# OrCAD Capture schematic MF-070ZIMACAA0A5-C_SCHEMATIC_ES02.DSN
size Custom; title: MF-070ZIMACAA0A5-C POWER BOARD; rev: ES02; note: 311-0701000005
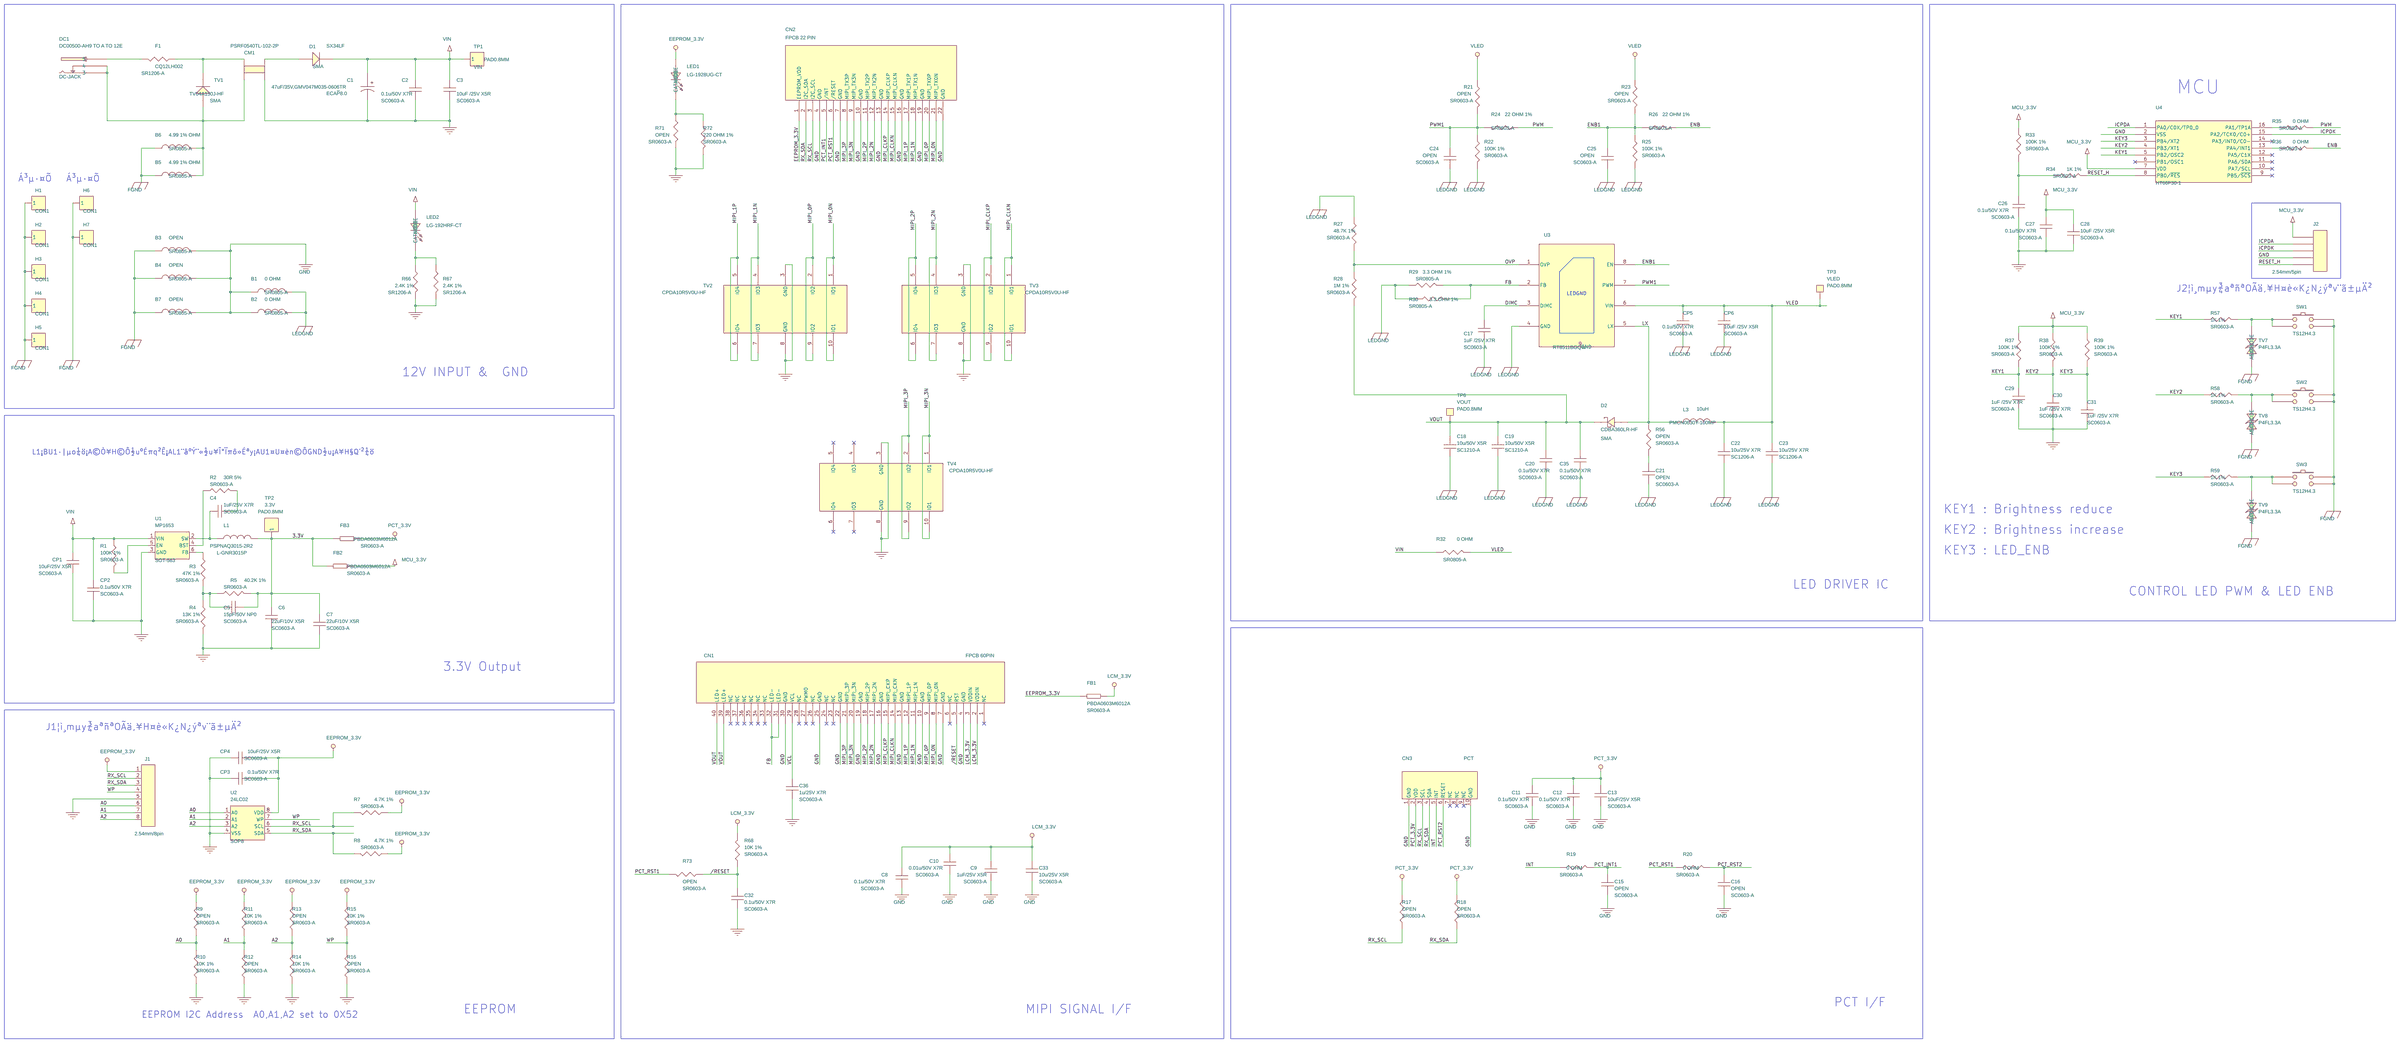
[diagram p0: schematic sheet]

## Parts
B1  0 OHM  [SR0805-A]
B2  0 OHM  [SR0805-A]
B3  OPEN  [SR0805-A]
B4  OPEN  [SR0805-A]
B5  4.99 1% OHM  [SR0805-A]
B6  4.99 1% OHM  [SR0805-A]
B7  OPEN  [SR0805-A]
C1  47uF/35V,GMV047M035-0606TR  [ECAP\8.0]
C2  0.1u/50V X7R  [SC0603-A]
C3  10uF /25V X5R  [SC0603-A]
C4  1uF/25V X7R  [SC0603-A]
C5  15pF/50V NP0  [SC0603-A]
C6  22uF/10V X5R  [SC0603-A]
C7  22uF/10V X5R  [SC0603-A]
C8  0.1u/50V X7R  [SC0603-A]
C9  1uF/25V X5R  [SC0603-A]
C10  0.01u/50V X7R  [SC0603-A]
C11  0.1u/50V X7R  [SC0603-A]
C12  0.1u/50V X7R  [SC0603-A]
C13  10uF/25V X5R  [SC0603-A]
C15  OPEN  [SC0603-A]
C16  OPEN  [SC0603-A]
C17  1uF /25V X7R  [SC0603-A]
C18  10u/50V X5R  [SC1210-A]
C19  10u/50V X5R  [SC1210-A]
C20  0.1u/50V X7R  [SC0603-A]
C21  OPEN  [SC0603-A]
C22  10u/25V X7R  [SC1206-A]
C23  10u/25V X7R  [SC1206-A]
C24  OPEN  [SC0603-A]
C25  OPEN  [SC0603-A]
C26  0.1u/50V X7R  [SC0603-A]
C27  0.1u/50V X7R  [SC0603-A]
C28  10uF /25V X5R  [SC0603-A]
C29  1uF /25V X7R  [SC0603-A]
C30  1uF /25V X7R  [SC0603-A]
C31  1uF /25V X7R  [SC0603-A]
C32  0.1u/50V X7R  [SC0603-A]
C33  10u/25V X5R  [SC0603-A]
C35  0.1u/50V X7R  [SC0603-A]
C36  1u/25V X7R  [SC0603-A]
CM1  PSRF0540TL-102-2P  [GDLW0504P]
CN1  FPCB 60PIN  [IC-HSD035E8N1]
CN2  FPCB 22 PIN  [IC-HSD035E8N1]
CN3  PCT  [FPCB 10 PIN]
CP1  10uF/25V X5R  [SC0603-A]
CP2  0.1u/50V X7R  [SC0603-A]
CP3  0.1u/50V X7R  [SC0603-A]
CP4  10uF/25V X5R  [SC0603-A]
CP5  0.1u/50V X7R  [SC0603-A]
CP6  10uF /25V X5R  [SC0603-A]
D1  SX34LF  [SMA]
D2  CDBA360LR-HF  [SMA]
DC1  DC00500-AH9 TO A TO 12E  [DC-JACK]
F1  CQ12LH002  [SR1206-A]
FB1  PBDA0603M6012A  [SR0603-A]
FB2  PBDA0603M6012A  [SR0603-A]
FB3  PBDA0603M6012A  [SR0603-A]
H1  CON1  [HOLE]
H2  CON1  [HOLE]
H3  CON1  [HOLE]
H4  CON1  [HOLE]
H5  CON1  [HOLE]
H6  CON1  [HOLE]
H7  CON1  [HOLE]
J1  2.54mm/8pin  [SIP\8P]
J2  2.54mm/5pin  [SIP\5P]
L1  PSPNAQ3015-2R2  [L-GNR3015P]
L3  10uH  [PMCN0630Y-100MP]
LED1  LG-1928UG-CT
LED2  LG-192HRF-CT
R1  100K 1%  [SR0603-A]
R2  30R 5%  [SR0603-A]
R3  47K 1%  [SR0603-A]
R4  13K 1%  [SR0603-A]
R5  40.2K 1%  [SR0603-A]
R7  4.7K 1%  [SR0603-A]
R8  4.7K 1%  [SR0603-A]
R9  OPEN  [SR0603-A]
R10  10K 1%  [SR0603-A]
R11  10K 1%  [SR0603-A]
R12  OPEN  [SR0603-A]
R13  OPEN  [SR0603-A]
R14  10K 1%  [SR0603-A]
R15  10K 1%  [SR0603-A]
R16  OPEN  [SR0603-A]
R17  OPEN  [SR0603-A]
R18  OPEN  [SR0603-A]
R19  0 OHM  [SR0603-A]
R20  0 OHM  [SR0603-A]
R21  OPEN  [SR0603-A]
R22  100K 1%  [SR0603-A]
R23  OPEN  [SR0603-A]
R24  22 OHM 1%  [SR0603-A]
R25  100K 1%  [SR0603-A]
R26  22 OHM 1%  [SR0603-A]
R27  48.7K 1%  [SR0603-A]
R28  1M 1%  [SR0603-A]
R29  3.3 OHM 1%  [SR0805-A]
R30  3.3 OHM 1%  [SR0805-A]
R32  0 OHM  [SR0805-A]
R33  100K 1%  [SR0603-A]
R34  1K 1%  [SR0603-A]
R35  0 OHM  [SR0603-A]
R36  0 OHM  [SR0603-A]
R37  100K 1%  [SR0603-A]
R38  100K 1%  [SR0603-A]
R39  100K 1%  [SR0603-A]
R56  OPEN  [SR0603-A]
R57  1K 1%  [SR0603-A]
R58  1K 1%  [SR0603-A]
R59  1K 1%  [SR0603-A]
R66  2.4K 1%  [SR1206-A]
R67  2.4K 1%  [SR1206-A]
R68  10K 1%  [SR0603-A]
R71  OPEN  [SR0603-A]
R72  220 OHM 1%  [SR0603-A]
R73  OPEN  [SR0603-A]
SW1  TS12H4.3
SW2  TS12H4.3
SW3  TS12H4.3
TP1  VIN  [PAD0.8MM]
TP2  3.3V  [PAD0.8MM]
TP3  VLED  [PAD0.8MM]
TP6  VOUT  [PAD0.8MM]
TV1  TV04A150J-HF  [SMA]
TV2  CPDA10R5V0U-HF  [SGP2510P8]
TV3  CPDA10R5V0U-HF  [SGP2510P8]
TV4  CPDA10R5V0U-HF  [SGP2510P8]
TV7  P4FL3.3A  [DIO_DFN0201_0-4]
TV8  P4FL3.3A  [DIO_DFN0201_0-4]
TV9  P4FL3.3A  [DIO_DFN0201_0-4]
U1  MP1653  [SOT-563]
U2  24LC02  [SOP8]
U3  RT8511BGQW  [DFN3_8_0-65_2]
U4  HT66F30-1  [NSOP-16P]

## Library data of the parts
B1-B7 L3 = INDUCTOR
C1 = ECAP_POL: Part Number: 117-00-3057
C2 C3 CP3 CP4 = CAP_NP0603: Part Number: 117-00-3036
C4 C5 = CAP_NP0603: Part Number: 117-00-3003
C6 C7 CP1 CP2 = CAP_NP0603: Part Number: 117-00-3043
C8-C13 C15-C28 C32 C33 C35 C36 CP5 CP6 = CAP_NP
C29-C31 = CAP_NP0603: Part Number: 117-00-3040
CM1 = INDUCTOR_2
CN1 = HANNSTAR_HSD035E8N1_6
CN2 = HANNSTAR_HSD035E8N1_7
CN3 = CON1_3
D1 = DIODE_1
D2 = DIODE_SCHOTTKY
DC1 = DC005_0: Part Description: DC JACK,DC005; Part Number: 226-00-3088
F1 R21-R30 R32 R33 R37-R39 R56-R59 = R
FB1-FB3 = BEAD0805: Part Number: 647-00-3000
H1-H7 TP1 TP2 = CON1
J1 = CON5_0
J2 = CON4_0
L1 = INDUCTOR0805: Part Number: 647-01-3059
LED1 LED2 = LED
R1 R3 R4 R66 R67 R71 R72 = RES0603: Part Number: 737-00-3068
R2 R5 = RES0603: Part Number: 737-00-3070
R7-R20 R68 R73 = RES0603: Part Number: 737-00-3060
R34-R36 = RES0603: Part Number: 737-00-3008
SW1-SW3 = SW_PUSHBUTTON_0
TP3 TP6 = TP_0
TV1 = DIODE_2
TV2-TV4 = RClamp3324P
TV7-TV9 = DIODE_TVS_DUAL: DIODE 1CH ESD PROTECTION FOR USB TYPE-C AND THUNDERBOLT3 X2SON2; Chkd/date: MANIRAJA/230920; Crtd /date: ALVY/230920; Custom_Duty: 15%; Customs_HS_Code: 85412900; Footprint Ref: SOD-123; Library Path: Y:\MIS_DATABASE\Library\ALTIUM_TOOL\SCHEMATICS_PARTS\MS_DISCRETE_Library.schlib; Mfr_name: TEXAS INSTRUMENTS; Mfr_part_number: TPD1E01B04DPLT; Mistral Part No: 130020090037-R; Package: X2SON2; Part_type: DIODE\TVS; Project: AM64X_SKEVM; RoHS: RoHS; Temperature: -40°C+125°C; Tolerance: NA; Voltage: NA; Wattage: NA; Weight: 0.2mg; Datasheet: Y:\MIS_DATABASE\DATASHEETS\DISCRETES\DIODES\TPD1E01B04.PDF
U1 = TD6810_0: Part Description: TD6810; Part Number: 427-00-3007
U2 = AT24C08: Part Number: 427-00-3002
U3 = RT8511_0
U4 = PIC16F873_SO_2

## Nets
3.3V: C5.2 C6.1 C7.1 FB2.1 FB3.1 L1.2 R5.2 TP2.1
GND: B1.1 B2.1 B3.2 B4.2 B7.2 C1.2 C2.2 C3.2 C6.2 C7.2 C8.2 C9.2 C10.2 C11.2 C12.2 C13.2 C15.2 C16.2 C26.2 C27.2 C28.2 C29.2 C30.2 C31.2 C32.2 C33.2 C36.2 CM1.3 CN1.4(GND) CN1.7(GND) CN1.10(GND) CN1.13(GND) CN1.16(GND) CN1.19(GND) CN1.22(GND) CN1.25(GND) CN1.30(GND) CN2.4(GND) CN2.7(GND) CN2.10(GND) CN2.13(GND) CN2.16(GND) CN2.19(GND) CN2.22(GND) CN3.1(GND) CN3.10(GND) CP1.2 CP2.2 CP3.1 CP4.1 J1.5 J2.4 R4.2 R10.1 R12.1 R14.1 R16.1 R66.2 R67.2 R71.2 R72.2 TV2.3(GND) TV2.8(GND) TV3.3(GND) TV3.8(GND) TV4.3(GND) TV4.8(GND) U1.3(GND) U2.4(VSS) U3.9(GND) U4.2(VSS)
VIN: C1.1 C2.1 C3.1 CP1.1 CP2.1 D1.2 LED2.1(ANODE) R1.1 R32.1 TP1.1 U1.1(VIN)
/RESET: C32.1 CN1.5(RST) R68.1 R73.1
A0: J1.6 R9.1 R10.2 U2.1(A0)
A1: J1.7 R11.1 R12.2 U2.2(A1)
A2: J1.8 R13.1 R14.2 U2.3(A2)
DIMC: C17.2 U3.3(DIMC)
EEPROM_3.3V: CN2.1(EEPROM_VDD) CP3.2 CP4.2 FB1.1 J1.1 LED1.1(ANODE) R7.1 R8.1 R9.2 R11.2 R13.2 R15.2 U2.8(VDD)
ENB: R26.1 R36.1
ENB1: C25.1 R23.2 R25.1 R26.2 U3.8(EN)
FB: CN1.31(LED-) CN1.32(LED-) R29.2 R30.2 U3.2(FB)
FGND: B3.1 B4.1 B5.1 B6.1 B7.1 H1.1 H2.1 H3.1 H4.1 H5.1 H6.1 H7.1 SW1.C SW1.D SW2.C SW2.D SW3.C SW3.D TV7.2(ANODE) TV8.2(ANODE) TV9.2(ANODE)
ICPDA: J2.2 U4.1(PA0/C0X/TP0_0)
ICPDK: J2.3 U4.15(PA2/TCK0/C0+)
INT: CN3.5(INT) R19.1
KEY1: C29.1 R37.2 R57.1 U4.5(PB2/OSC2)
KEY2: C30.1 R38.2 R58.1 U4.4(PB3/XT1)
KEY3: C31.1 R39.2 R59.1 U4.3(PB4/XT2)
LCM_3.3V: C8.1 C9.1 C10.1 C33.1 CN1.2(VDDIN) CN1.3(VDDIN) FB1.2 R68.2
LEDGND: B1.2 B2.2 C17.1 C18.1 C19.1 C20.1 C21.2 C22.1 C23.1 C24.2 C25.2 C35.1 CP5.2 CP6.2 R22.2 R25.2 R27.1 R29.1 R30.1 U3.4(GND)
LX: D2.1(ANODE) L3.1 R56.1 U3.5(LX)
MCU_3.3V: C27.1 C28.1 FB2.2 J2.1 R33.1 R37.1 R38.1 R39.1 U4.7(VDD)
MIPI_0N: CN1.8(MIPI_0N) CN2.21(MIPI_TX0N) TV2.1(IO1) TV2.10(IO1)
MIPI_0P: CN1.9(MIPI_0P) CN2.20(MIPI_TX0P) TV2.2(IO2) TV2.9(IO2)
MIPI_1N: CN1.11(MIPI_1N) CN2.18(MIPI_TX1N) TV2.4(IO3) TV2.7(IO3)
MIPI_1P: CN1.12(MIPI_1P) CN2.17(MIPI_TX1P) TV2.5(IO4) TV2.6(IO4)
MIPI_2N: CN1.17(MIPI_2N) CN2.12(MIPI_TX2N) TV3.4(IO3) TV3.7(IO3)
MIPI_2P: CN1.18(MIPI_2P) CN2.11(MIPI_TX2P) TV3.5(IO4) TV3.6(IO4)
MIPI_3N: CN1.20(MIPI_3N) CN2.9(MIPI_TX3N) TV4.1(IO1) TV4.10(IO1)
MIPI_3P: CN1.21(MIPI_3P) CN2.8(MIPI_TX3P) TV4.2(IO2) TV4.9(IO2)
MIPI_CLKN: CN1.14(MIPI_CKN) CN2.15(MIPI_CLKN) TV3.1(IO1) TV3.10(IO1)
MIPI_CLKP: CN1.15(MIPI_CKP) CN2.14(MIPI_CLKP) TV3.2(IO2) TV3.9(IO2)
OVP: R27.2 R28.1 U3.1(OVP)
PCT_3.3V: C11.1 C12.1 C13.1 CN3.2(VDD) FB3.2 R17.2 R18.2
PCT_INT1: C15.1 CN2.5(/INT) R19.2
PCT_RST1: CN2.6(/RESET) R20.1 R73.2
PCT_RST2: C16.1 CN3.6(RESET) R20.2
PWM: R24.1 R35.1
PWM1: C24.1 R21.2 R22.1 R24.2 U3.7(PWM)
RESET_H: J2.5 R34.1 U4.8(PB0/~{RES})
RX_SCL: CN2.3(I2C_SCL) CN3.3(SCL) J1.2 R7.2 R17.1 U2.6(SCL)
RX_SDA: CN2.2(I2C_SDA) CN3.4(SDA) J1.3 R8.2 R18.1 U2.5(SDA)
VCL: C36.1 CN1.29(VCL)
VLED: C22.2 C23.2 CP5.1 CP6.1 L3.2 R21.1 R23.1 R32.2 TP3.1(TP) U3.6(VIN)
VOUT: C18.2 C19.2 C20.2 C35.2 CN1.39(LED+) CN1.40(LED+) D2.2(CATHODE) R28.2 TP6.1(TP)
WP: J1.4 R15.1 R16.2 U2.7(WP)
N14289089: DC1.5 F1.2
N14289101: CM1.1 F1.1 TV1.2
N14289105: CM1.2 D1.1
N14289125: B5.2 B6.2 CM1.4 DC1.3 DC1.4 TV1.1
N14506503: C21.1 R56.2
N14509647: R2.1 U1.4(BST)
N14509651: C4.2 R2.2
N14509727: C4.1 L1.1 U1.2(SW)
N14509879: R1.2 U1.5(EN)
N14509925: R3.1 U1.6(FB)
N14510061: C5.1 R3.2 R4.1 R5.1
N14543357: C26.1 R33.2 R34.2
N14572856: R36.2 U4.13(PA4/INT1)
N14573902: R57.2 SW1.A SW1.B TV7.1(CATHODE)
N14573940: R58.2 SW2.A SW2.B TV8.1(CATHODE)
N14573978: R59.2 SW3.A SW3.B TV9.1(CATHODE)
N14631898: R35.2 U4.16(PA1/TP1A)
N14687410: LED2.2(CATHODE) R66.1 R67.1
N14705498: LED1.2(CATHODE) R71.1 R72.1

Not connected (* = marked no-connect by the designer): CN1 1(NC)* 6(NC)* 23(NC)* 24(NC)* 26(NC)* 27(PWMO)* 28(NC)* 33(NC)* 34(NC)* 35(NC)* 36(NC)* 37(NC)* 38(NC)*; CN3 7(NC)* 8(NC)* 9(NC)*; TV4 4(IO3)* 5(IO4)* 6(IO4)* 7(IO3)*; U4 6(PB1/OSC1)* 9(PB5/~{SCS})* 10(PA7/SCL)* 11(PA6/SDA)* 12(PA5/C1X)* 14(PA3/INT0/C0-)*

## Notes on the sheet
- MCU
- Á³µ·¤Õ
- Á³µ·¤Õ
- J2¦ì¸mµy¾aªñªOÃä,¥H¤è«K¿N¿ýªv¨ã±µÄ²
- LEDGND
- 12V INPUT &  GND
- L1¡BU1·|µo¼ö¡A©Ò¥H©Ô½uºÉ¶q²Ê¡AL1¨âºÝ¨«½u¥Î°Ï¶ô»Éªy¡AU1¤U¤è­n©ÔGND½u¡A¥H§Q´²¼ö
- KEY1 : Brightness reduce
- KEY2 : Brightness increase
- KEY3 : LED_ENB
- LED DRIVER IC
- CONTROL LED PWM & LED ENB
- 3.3V Output
- J1¦ì¸mµy¾aªñªOÃä,¥H¤è«K¿N¿ýªv¨ã±µÄ²
- PCT I/F
- EEPROM
- MIPI SIGNAL I/F
- EEPROM I2C Address  A0,A1,A2 set to 0X52
